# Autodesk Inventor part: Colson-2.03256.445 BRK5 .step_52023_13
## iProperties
Created: 2010-10
Part Number: Colson-2.03256.445 BRK5 .step_52023_13
Document SubType Name: Modeling
Designer: Administrator
Density: 7.85 g/cm^3
Material: Steel
Mass: 34.2353 g
Surface Area: 84.1634 cm^2
Volume: 4.36118 cm^3
Author: Administrator
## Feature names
1. Base1
